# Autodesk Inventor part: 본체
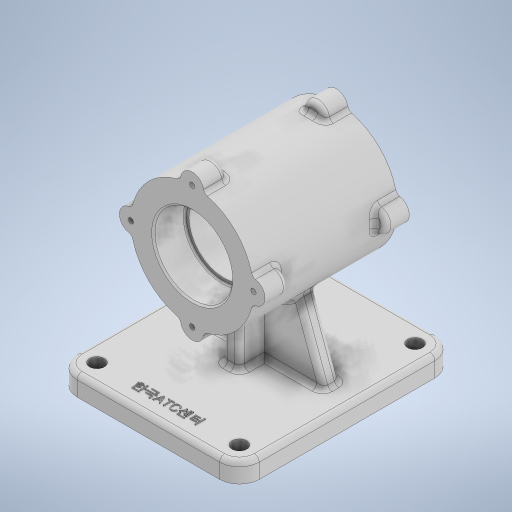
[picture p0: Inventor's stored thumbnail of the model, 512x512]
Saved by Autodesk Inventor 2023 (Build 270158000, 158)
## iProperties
Created: 2023-08
Part Number: 본체
Material: 일반
Document SubType Name: Modeling
Designer: asung
Density: 1 g/cm^3
Appearance: 기본값
Author: asung
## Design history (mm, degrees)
sketch "스케치1"
  geometry: L1 (43, 65)-(-43, 65); L2 (-55, 53)-(-55, -53); L3 (-43, -65)-(43, -65); L4 (55, -53)-(55, 53); L5 (55, 65)-(-55, -65); L6 (-55, 65)-(55, -65); C1 r 4.5 at (43, -53); C2 r 4.5 at (-43, -53); C3 r 4.5 at (-43, 53); C4 r 4.5 at (43, 53); A1 r 12 centre (43, 53) between (55, 53) and (43, 65); A2 r 12 centre (43, -53) between (43, -65) and (55, -53); A3 r 12 centre (-43, -53) between (-55, -53) and (-43, -65); A4 r 12 centre (-43, 53) between (-43, 65) and (-55, 53); 1 further point
  constraints: 12 end point, 8 centre point, 8 point on circle, 8 point on line, 8 tangent, 4 coincident, 3 equal radius, 2 midpoint, 2 parallel, 1 horizontal, 1 perpendicular
  dimensions: "d0" = 110 distance of L6.end L5.end; "d1" = 130 distance of L5.end L6.start; "d2" = 12 radius of A1; "d3" = 9 diameter of C1; "d4" = 9 diameter of C2; "d5" = 9 diameter of C3; "d6" = 9 diameter of C4
extrude "돌출1" new body sketch "스케치1" distance "d7" = 12; taper "d8" = 0 deg
fillet "모깎기1" dims "d9" = 3
node "작업 평면1"
node "작업 평면2"
sketch "스케치3"
  geometry: L1 (-9, 12)-(95, 12) reference; L2 (98, 9)-(98, 0) reference; L3 (98, 0)-(-12, 0) reference; L4 (-12, 0)-(-12, 9) reference; L5 (43, 0)-(43, 82); C1 r 37 at (43, 82); A1 r 3 centre (-9, 9) between (-9, 12) and (-12, 9) reference; A2 r 3 centre (95, 9) between (98, 9) and (95, 12) reference
  constraints: 2 end point, 1 centre point, 1 coincident, 1 vertical
  dimensions: "d12" = 82 distance of L5.start L5.end; "d13" = 74 diameter of C1
extrude "돌출2" join sketch "스케치3" stored distance "d14" = 87; taper "d15" = 0 deg
sketch "스케치4"
  geometry: C1 r 7 at (0, 37); 4 further points
  constraints: 1 centre point, 2 other
  dimensions: "d16" = 14 diameter of C1
extrude "돌출3" join sketch "스케치4" distance "d17" = 14; taper "d18" = 0 deg
sketch "스케치5"
  geometry: A1 r 7 centre (43, 119) between (49.969, 118.338) and (36.031, 118.338) reference; 2 further points
  constraints: 1 coincident
hole "구멍1" sketch "스케치5" at (43, 119) diameter "d19" = 3.242; stored, may be unused: countersink angle "d23" = 90 deg, drill point angle "d25" = 118 deg; dims "d20" = 8, "d21" = 4, "d22" = 2, "d24" = 10
fillet "모깎기2" dims "d26" = 3
fillet "모깎기3" dims "d27" = 3
node "작업 평면3"
sketch "스케치6"
  geometry: L1 (12, 62)-(12, -62) reference; L2 (9, -65)-(0, -65) reference; L3 (0, -65)-(0, 65) reference; L4 (0, 65)-(9, 65) reference; L5 (119, 27.526)-(120.621, 28.5) reference; L6 (120.621, 28.5)-(120.621, 38.5) reference; L7 (120.621, 38.5)-(126, 38.5) reference; L8 (126, 38.5)-(126, 27.5) reference; L9 (123, 24.5)-(122, 24.5) reference; L10 (119, 21.5)-(119, -31.5) reference; L11 (122, -34.5)-(123, -34.5) reference; L12 (126, -37.5)-(126, -48.5) reference; L13 (126, -48.5)-(120.621, -48.5) reference; L14 (120.621, -48.5)-(120.621, -38.5) reference; L15 (120.621, -38.5)-(119, -37.526) reference; L16 (119, -37.526)-(117.379, -38.5) reference; L17 (117.379, -38.5)-(117.379, -48.5) reference; L18 (117.379, -48.5)-(46.621, -48.5) reference; L19 (46.621, -48.5)-(46.621, -38.5) reference; L20 (46.621, -38.5)-(45, -37.526) reference; L21 (45, -37.526)-(43.379, -38.5) reference; L22 (43.379, -38.5)-(43.379, -48.5) reference; L23 (43.379, -48.5)-(38, -48.5) reference; L24 (38, -48.5)-(38, -37.5) reference; L25 (41, -34.5)-(42, -34.5) reference; L26 (45, -31.5)-(45, 21.5) reference; L27 (42, 24.5)-(41, 24.5) reference; L28 (38, 27.5)-(38, 38.5) reference; L29 (38, 38.5)-(43.379, 38.5) reference; L30 (43.379, 38.5)-(43.379, 28.5) reference; L31 (43.379, 28.5)-(45, 27.526) reference; L32 (45, 27.526)-(46.621, 28.5) reference; L33 (46.621, 28.5)-(46.621, 38.5) reference; L34 (46.621, 38.5)-(117.379, 38.5) reference; L35 (117.379, 38.5)-(117.379, 28.5) reference; L36 (117.379, 28.5)-(119, 27.526) reference; L37 (88.889, 38.5)-(75.111, 38.5) reference; L38 (82, 38.5)-(82, -48.5); L39 (83.621, -48.5)-(80.379, -48.5) reference; L40 (82, 38.5)-(105.5, 38.5); L41 (117.863, 38.5)-(91.104, 38.5) reference; L42 (105.5, 38.5)-(105.5, 20.5); L43 (104.5, 19.5)-(103, 19.5); L44 (82, -48.5)-(105.5, -48.5); L45 (91.104, -48.5)-(117.863, -48.5) reference; L46 (105.5, -48.5)-(105.5, -30.5); L47 (104.5, -29.5)-(103, -29.5); L48 (103, -29.5)-(103, 19.5); A1 r 3 centre (9, 62) between (12, 62) and (9, 65) reference; A2 r 3 centre (9, -62) between (9, -65) and (12, -62) reference; A3 r 3 centre (123, 27.5) between (123, 24.5) and (126, 27.5) reference; A4 r 3 centre (122, 21.5) between (122, 24.5) and (119, 21.5) reference; A5 r 3 centre (122, -31.5) between (119, -31.5) and (122, -34.5) reference; A6 r 3 centre (123, -37.5) between (126, -37.5) and (123, -34.5) reference; A7 r 3 centre (41, -37.5) between (41, -34.5) and (38, -37.5) reference; A8 r 3 centre (42, -31.5) between (42, -34.5) and (45, -31.5) reference; A9 r 3 centre (42, 21.5) between (45, 21.5) and (42, 24.5) reference; A10 r 3 centre (41, 27.5) between (38, 27.5) and (41, 24.5) reference; A11 r 1 centre (104.5, 20.5) between (104.5, 19.5) and (105.5, 20.5); A12 r 1 centre (104.5, -30.5) between (105.5, -30.5) and (104.5, -29.5); 7 further points
  constraints: 16 end point, 6 point on line, 4 point on circle, 4 tangent, 3 perpendicular, 2 centre point, 2 midpoint, 1 equal radius, 1 vertical
  dimensions: "d31" = 23.5 distance of L38.start L40.end; "d32" = 19 distance of L40.end point (105.5, 19.5); "d33" = 2.5 distance of point (105.5, 19.5) L43.end; "d34" = 23.5 distance of L38.end L44.end; "d35" = 19 distance of L44.end point (105.5, -29.5); "d36" = 2.5 distance of point (105.5, -29.5) L47.end; "d37" = 1 radius of A11
revolve "회전1" sketch "스케치6" stored, may be unused: angle "d38" = 90 deg
chamfer "모따기1" distance "d39" = 1; stored, may be unused: second distance "d40" = 2, angle "d41" = 45 deg
sketch "스케치7"
  geometry: L1 (-43, -65)-(43, -65) reference; L2 (-55, 53)-(-55, -53) reference; L3 (43, 65)-(-43, 65) reference; L4 (55, -53)-(55, 53) reference; L5 (0, -65)-(0, 5); L6 (-5, -15)-(5, -15); L7 (5, -15)-(5, 25); L8 (5, 25)-(-5, 25); L9 (-5, 25)-(-5, -15); L10 (-5, -15)-(5, 25); L11 (5, -15)-(-5, 25); C1 r 4.5 at (-43, -53) reference; C2 r 4.5 at (43, -53) reference; C3 r 4.5 at (43, 53) reference; C4 r 4.5 at (-43, 53) reference; A1 r 12 centre (43, -53) between (43, -65) and (55, -53) reference; A2 r 12 centre (-43, -53) between (-55, -53) and (-43, -65) reference; A3 r 12 centre (-43, 53) between (-43, 65) and (-55, 53) reference; A4 r 12 centre (43, 53) between (55, 53) and (43, 65) reference; 1 further point
  constraints: 14 end point, 3 midpoint, 2 parallel, 1 horizontal, 1 perpendicular, 1 vertical
  dimensions: "d42" = 70 distance of L5.start L5.end; "d43" = 10 distance of L8.end L7.end; "d44" = 40 distance of L7.end L6.end
extrude "돌출4" join sketch "스케치7" stored distance "d45" = 14; taper "d46" = 0 deg
node "작업 평면4"
sketch "스케치8"
  geometry: L1 (-9, 12)-(38, 12) reference; L2 (38, 12)-(38, 45.339) reference; L3 (48, 45.339)-(48, 12) reference; L4 (48, 12)-(95, 12) reference; L5 (98, 9)-(98, 0) reference; L6 (98, 0)-(-12, 0) reference; L7 (-12, 0)-(-12, 9) reference; L8 (98, 12)-(84, 12); L9 (81.5, 12)-(90.5, 12) reference; L10 (84, 12)-(66.128, 61.104); L11 (-12, 12)-(2, 12); L12 (2, 12)-(20.401, 62.557); L13 (20.401, 62.557)-(38, 48.571); L14 (38, 12)-(38, 45.339) reference; L15 (38, 48.571)-(38, 12); L16 (66.128, 61.104)-(48, 50.911); L17 (48, 12)-(48, 45.339) reference; L18 (48, 50.911)-(48, 12); C1 r 21 at (43, 82) reference; A1 r 3 centre (-9, 9) between (-9, 12) and (-12, 9) reference; A2 r 37 centre (43, 82) between (48, 45.339) and (38, 45.339) reference; A3 r 3 centre (95, 9) between (98, 9) and (95, 12) reference; 4 further points
  constraints: 16 end point, 2 collinear, 2 point on line
  dimensions: "d47" = 14 distance of L8.start L8.end; "d48" = 110 deg angle of L4 L10; "d49" = 14 distance of L11.start L11.end; "d50" = 110 deg angle of L1 L12
extrude "돌출5" join sketch "스케치8" stored distance "d51" = 10; taper "d52" = 0 deg
fillet "모깎기4" dims "d53" = 3
fillet "모깎기5" dims "d54" = 3
fillet "모깎기6" dims "d55" = 3
sketch "스케치9"
  geometry: L1 (43, 65)-(-43, 65) reference; 2 further points
  constraints: 1 other
  dimensions: "d57" = 118 distance from line of point (0, -53) L1
feature "엠보싱1" sketch "스케치9" dims "d0" = 110, "d1" = 130, "d2" = 12, "d3" = 9, "d4" = 9, "d5" = 9, "d6" = 9, "d58" = 0.5, "d59" = 0
node "솔리드1"
pattern_circular "원형 패턴1" dims "d29" = 360 deg
mirror "미러1"
node "투영된 루프1"
node "절단 모서리 투영2"
node "절단 모서리 투영3"
node "절단 모서리 투영4"
feature "A9D066F2-1C7D-4E18-AEED-F7BC21143FA4" dims "d19" = 3.242, "d20" = 8, "d21" = 4, "d22" = 2, "d23" = 90 deg, "d24" = 10, "d25" = 118 deg
